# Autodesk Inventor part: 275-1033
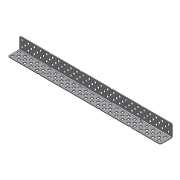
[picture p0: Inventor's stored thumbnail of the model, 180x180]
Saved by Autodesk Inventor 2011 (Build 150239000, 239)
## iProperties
Company: Autodesk Inc.
Created: 2005-08
Part Number: 275-1033
Document SubType Name: Sheet Metal
Designer: Autodesk Inc.
Density: 1 g/cm^3
Sheet Metal Rule: Default
Catalog Web Link: http://www.vexrobotics.com/chassis-kit.html
Description: 2x2x25 Bumper. This part has holes on 0.500" increments. This part is a versatile angle used in the medium chassis kit.
Vendor: Innovation First, Inc.
Author: Autodesk Inc.
Title: VEX Robotics Kit of Parts
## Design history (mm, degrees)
node "Face2"
  sketch "Sketch1"
    geometry: L1 (-158.75, 22.86)-(158.75, 22.86); L2 (-155.956, 19.939)-(-151.384, 19.939); L3 (-151.384, 19.939)-(-151.384, 15.367); L4 (-151.384, 15.367)-(-155.956, 15.367); L5 (-155.956, 15.367)-(-155.956, 19.939); L6 (-155.956, 7.239)-(-151.384, 7.239); L7 (-151.384, 7.239)-(-151.384, 2.667); L8 (-151.384, 2.667)-(-155.956, 2.667); L9 (-155.956, 2.667)-(-155.956, 7.239); L10 (-143.256, 19.939)-(-138.684, 19.939); L11 (-138.684, 19.939)-(-138.684, 15.367); L12 (-138.684, 15.367)-(-143.256, 15.367); L13 (-143.256, 15.367)-(-143.256, 19.939); L14 (-143.256, 7.239)-(-138.684, 7.239); L15 (-138.684, 7.239)-(-138.684, 2.667); L16 (-138.684, 2.667)-(-143.256, 2.667); L17 (-143.256, 2.667)-(-143.256, 7.239); L18 (-149.606, 9.017)-(-149.606, 13.589); L19 (-149.606, 13.589)-(-145.034, 13.589); L20 (-145.034, 9.017)-(-149.606, 9.017); L21 (-145.034, 13.589)-(-145.034, 9.017); L22 (-136.906, 9.017)-(-136.906, 13.589); L23 (-132.334, 9.017)-(-136.906, 9.017); L24 (-136.906, 13.589)-(-132.334, 13.589); L25 (-132.334, 13.589)-(-132.334, 9.017); L26 (-130.556, 15.367)-(-130.556, 19.939); L27 (-130.556, 2.667)-(-130.556, 7.239); L28 (-125.984, 2.667)-(-130.556, 2.667); L29 (-125.984, 7.239)-(-125.984, 2.667); L30 (-130.556, 7.239)-(-125.984, 7.239); L31 (-125.984, 15.367)-(-130.556, 15.367); L32 (-130.556, 19.939)-(-125.984, 19.939); L33 (-125.984, 19.939)-(-125.984, 15.367); L34 (-124.206, 9.017)-(-124.206, 13.589); L35 (-119.634, 9.017)-(-124.206, 9.017); L36 (-124.206, 13.589)-(-119.634, 13.589); L37 (-119.634, 13.589)-(-119.634, 9.017); L38 (-117.856, 15.367)-(-117.856, 19.939); L39 (-117.856, 2.667)-(-117.856, 7.239); L40 (-113.284, 2.667)-(-117.856, 2.667); L41 (-113.284, 7.239)-(-113.284, 2.667); L42 (-117.856, 7.239)-(-113.284, 7.239); L43 (-113.284, 15.367)-(-117.856, 15.367); L44 (-117.856, 19.939)-(-113.284, 19.939); L45 (-113.284, 19.939)-(-113.284, 15.367); L46 (-111.506, 9.017)-(-111.506, 13.589); L47 (-106.934, 9.017)-(-111.506, 9.017); L48 (-111.506, 13.589)-(-106.934, 13.589); L49 (-106.934, 13.589)-(-106.934, 9.017); L50 (-105.156, 15.367)-(-105.156, 19.939); L51 (-105.156, 2.667)-(-105.156, 7.239); L52 (-100.584, 2.667)-(-105.156, 2.667); L53 (-100.584, 7.239)-(-100.584, 2.667); L54 (-105.156, 7.239)-(-100.584, 7.239); L55 (-100.584, 15.367)-(-105.156, 15.367); L56 (-105.156, 19.939)-(-100.584, 19.939); L57 (-100.584, 19.939)-(-100.584, 15.367); L58 (-98.806, 9.017)-(-98.806, 13.589); L59 (-94.234, 9.017)-(-98.806, 9.017); L60 (-98.806, 13.589)-(-94.234, 13.589); L61 (-94.234, 13.589)-(-94.234, 9.017); L62 (-92.456, 15.367)-(-92.456, 19.939); L63 (-92.456, 2.667)-(-92.456, 7.239); L64 (-87.884, 2.667)-(-92.456, 2.667)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; 2 further points
    constraints: 600 end point, 12 parallel, 8 collinear, 7 horizontal, 6 perpendicular, 1 coincident, 1 midpoint, 552 other
    dimensions: "d20" = 2.794 distance between parallel lines of L192 L5; "d22" = 2.921 distance between parallel lines of L1 L2; "d23" = 22.86 distance between parallel lines of L191 L1; "d24" = 4.572 distance of L4.end L2.start; "d25" = 8.128 distance between parallel lines of L6 L4; "d26" = 4.572 distance of L8.end L6.start; "d125" = 317.5 distance of L190.end L191.end; "d126" = 4.572 distance of L2.start L2.end; "d127" = 4.572 distance of L18.end L19.end; "d128" = 4.572 distance of L19.end L20.start; "d129" = 9.017 distance between parallel lines of L191 L20; "d130" = 9.144 distance between parallel lines of L192 L18; "d133" = 15.494 distance between parallel lines of L192 L13; "d134" = 4.572 distance of L10.start L10.end
node "Flange8"
sketch "Sketch15"
  geometry: L1 (0, 0)-(0, 22.86) reference; L2 (0, 0)-(317.5, 0) reference; L3 (2.794, 2.921)-(7.366, 2.921); L4 (7.366, 2.921)-(7.366, 7.493); L5 (7.366, 7.493)-(2.794, 7.493); L6 (2.794, 7.493)-(2.794, 2.921); L7 (2.794, 15.621)-(7.366, 15.621); L8 (7.366, 15.621)-(7.366, 20.193); L9 (7.366, 20.193)-(2.794, 20.193); L10 (2.794, 20.193)-(2.794, 15.621); L11 (9.144, 9.017)-(13.716, 9.017); L12 (13.716, 9.017)-(13.716, 13.589); L13 (13.716, 13.589)-(9.144, 13.589); L14 (9.144, 13.589)-(9.144, 9.017); L15 (15.494, 15.621)-(20.066, 15.621); L16 (20.066, 15.621)-(20.066, 20.193); L17 (20.066, 20.193)-(15.494, 20.193); L18 (15.494, 20.193)-(15.494, 15.621); L19 (15.494, 7.493)-(20.066, 7.493); L20 (20.066, 7.493)-(20.066, 2.921); L21 (20.066, 2.921)-(15.494, 2.921); L22 (15.494, 2.921)-(15.494, 7.493); L23 (21.844, 13.589)-(21.844, 9.017); L24 (21.844, 9.017)-(26.416, 9.017); L25 (26.416, 13.589)-(21.844, 13.589); L26 (28.194, 2.921)-(28.194, 7.493); L27 (26.416, 9.017)-(26.416, 13.589); L28 (32.766, 7.493)-(32.766, 2.921); L29 (32.766, 2.921)-(28.194, 2.921); L30 (28.194, 7.493)-(32.766, 7.493); L31 (28.194, 20.193)-(28.194, 15.621); L32 (28.194, 15.621)-(32.766, 15.621); L33 (32.766, 15.621)-(32.766, 20.193); L34 (32.766, 20.193)-(28.194, 20.193); L35 (34.544, 13.589)-(34.544, 9.017); L36 (34.544, 9.017)-(39.116, 9.017); L37 (39.116, 13.589)-(34.544, 13.589); L38 (40.894, 2.921)-(40.894, 7.493); L39 (39.116, 9.017)-(39.116, 13.589); L40 (45.466, 7.493)-(45.466, 2.921); L41 (45.466, 2.921)-(40.894, 2.921); L42 (40.894, 7.493)-(45.466, 7.493); L43 (40.894, 20.193)-(40.894, 15.621); L44 (40.894, 15.621)-(45.466, 15.621); L45 (45.466, 15.621)-(45.466, 20.193); L46 (45.466, 20.193)-(40.894, 20.193); L47 (47.244, 13.589)-(47.244, 9.017); L48 (47.244, 9.017)-(51.816, 9.017); L49 (51.816, 13.589)-(47.244, 13.589); L50 (53.594, 2.921)-(53.594, 7.493); L51 (51.816, 9.017)-(51.816, 13.589); L52 (58.166, 7.493)-(58.166, 2.921); L53 (58.166, 2.921)-(53.594, 2.921); L54 (53.594, 7.493)-(58.166, 7.493); L55 (53.594, 20.193)-(53.594, 15.621); L56 (53.594, 15.621)-(58.166, 15.621); L57 (58.166, 15.621)-(58.166, 20.193); L58 (58.166, 20.193)-(53.594, 20.193); L59 (59.944, 13.589)-(59.944, 9.017); L60 (59.944, 9.017)-(64.516, 9.017); L61 (64.516, 13.589)-(59.944, 13.589); L62 (66.294, 2.921)-(66.294, 7.493); L63 (64.516, 9.017)-(64.516, 13.589); L64 (70.866, 7.493)-(70.866, 2.921)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; 1 further point
  constraints: 592 end point, 10 parallel, 8 collinear, 6 horizontal, 5 perpendicular, 552 other
  dimensions: "d148" = 2.921 distance between parallel lines of L2 L3; "d149" = 4.572 distance of L5.end L3.start; "d150" = 8.128 distance between parallel lines of L7 L5; "d151" = 4.572 distance of L9.end L7.start; "d152" = 2.794 distance between parallel lines of L1 L6; "d153" = 4.572 distance of L3.start L3.end; "d154" = 9.144 distance between parallel lines of L1 L14; "d155" = 4.572 distance of L11.start L11.end; "d156" = 4.572 distance of L13.end L11.start; "d157" = 15.494 distance between parallel lines of L1 L18; "d158" = 4.572 distance of L16.end L17.end; "d159" = 9.017 distance between parallel lines of L2 L11; "d162" = 12.7 distance of L19.end L28.start
cut "Cut4" sketch "Sketch15" dims "d167" = 1.27 (= Thickness), "d168" = 0
sketch "Sketch16" dims "d175" = 25.4
  geometry: L1 (-158.75, 22.86)-(158.75, 22.86) reference; L2 (-158.75, 0)-(-158.75, 22.86) reference; L3 (158.75, 0)-(-158.75, 0) reference; L4 (-158.75, 20.955)-(-156.845, 22.86); L5 (-156.845, 22.86)-(-160.655, 22.86); L6 (-160.655, 22.86)-(-158.75, 20.955); L7 (-95.25, 20.955)-(-93.345, 22.86); L8 (-93.345, 22.86)-(-97.155, 22.86); L9 (-97.155, 22.86)-(-95.25, 20.955); L10 (-31.75, 20.955)-(-29.845, 22.86); L11 (-29.845, 22.86)-(-33.655, 22.86); L12 (-33.655, 22.86)-(-31.75, 20.955); L13 (31.75, 20.955)-(33.655, 22.86); L14 (33.655, 22.86)-(29.845, 22.86); L15 (29.845, 22.86)-(31.75, 20.955); L16 (95.25, 20.955)-(97.155, 22.86); L17 (97.155, 22.86)-(93.345, 22.86); L18 (93.345, 22.86)-(95.25, 20.955); L19 (158.75, 20.955)-(160.655, 22.86); L20 (160.655, 22.86)-(156.845, 22.86); L21 (156.845, 22.86)-(158.75, 20.955); 1 further point
  constraints: 36 end point, 2 perpendicular, 2 point on line, 1 horizontal, 1 parallel, 30 other
  dimensions: "d169" = 1.905 horizontal distance of L4.start L4.end; "d172" = 63.5 distance of L4.end L7.end
cut "Cut5" sketch "Sketch16" dims "d177" = 1.27 (= Thickness), "d178" = 0
sketch "Sketch17" dims "d185" = 25.4
  geometry: L1 (0, 0)-(0, 22.86) reference; L2 (0, 0)-(317.5, 0) reference; L3 (317.5, 0)-(317.5, 22.86) reference; L4 (0, 1.905)-(1.905, 0); L5 (1.905, 0)-(-1.905, 0); L6 (-1.905, 0)-(0, 1.905); L7 (63.5, 1.905)-(65.405, 0); L8 (65.405, 0)-(61.595, 0); L9 (61.595, 0)-(63.5, 1.905); L10 (127, 1.905)-(128.905, 0); L11 (128.905, 0)-(125.095, 0); L12 (125.095, 0)-(127, 1.905); L13 (190.5, 1.905)-(192.405, 0); L14 (192.405, 0)-(188.595, 0); L15 (188.595, 0)-(190.5, 1.905); L16 (254, 1.905)-(255.905, 0); L17 (255.905, 0)-(252.095, 0); L18 (252.095, 0)-(254, 1.905); L19 (317.5, 1.905)-(319.405, 0); L20 (319.405, 0)-(315.595, 0); L21 (315.595, 0)-(317.5, 1.905); 1 further point
  constraints: 36 end point, 3 perpendicular, 2 point on line, 1 horizontal, 30 other
  dimensions: "d179" = 1.905 horizontal distance of L5.end L4.start; "d182" = 63.5 distance of L4.end L7.end
cut "Cut6" sketch "Sketch17" dims "d187" = 1.27 (= Thickness), "d188" = 0
sketch "Sketch18" dims "d196" = 25.4
  geometry: L1 (317.5, 0)-(0, 0) reference; L2 (65.405, -22.86)-(125.095, -22.86) reference; L3 (61.595, 1.118)-(63.5, -0.787); L4 (63.5, -0.787)-(65.405, 1.118); L5 (65.405, 1.118)-(63.5, 3.023); L6 (63.5, 3.023)-(61.595, 1.118); L7 (128.905, 1.118)-(127, 3.023); L8 (125.095, 1.118)-(127, -0.787); L9 (127, 3.023)-(125.095, 1.118); L10 (127, -0.787)-(128.905, 1.118); L11 (192.405, 1.118)-(190.5, 3.023); L12 (188.595, 1.118)-(190.5, -0.787); L13 (190.5, 3.023)-(188.595, 1.118); L14 (190.5, -0.787)-(192.405, 1.118); L15 (255.905, 1.118)-(254, 3.023); L16 (252.095, 1.118)-(254, -0.787); L17 (254, 3.023)-(252.095, 1.118); L18 (254, -0.787)-(255.905, 1.118); 2 further points
  constraints: 32 end point, 2 parallel, 2 perpendicular, 1 horizontal, 1 horizontal alignment, 1 vertical alignment, 24 other
  dimensions: "d189" = 1.1176 distance from line of L1 L3.start; "d190" = 1.905 horizontal distance of L5.end L3.start; "d193" = 63.5 distance of L4.end L7.start
cut "Cut7" sketch "Sketch18" dims "d198" = 1.27 (derived), "d199" = 0
body "Solid1"
face "Plate9" dims "Thickness" = 1.27
sketch "Sketch14"
  geometry: L1 (0, 22.86)-(-317.5, 22.86); L2 (-317.5, 22.86)-(-317.5, 0); 2 other entities
  constraints: 4 end point, 4 other
face "Plate10" dims "d138" = 1.27 (= BendReliefWidth), "d139" = 0.635 (= BendReliefDepth), "d140" = 2.54 (= MinimumRemnant), "d141" = 1.27 (= BendRadius), "d142" = 25.4, "d143" = 90 deg, "d144" = 1.27 (= BendRadius), "d145" = 5.08 (= CornerReliefSize), "d146" = 1.27 (= GapSize), "d147" = 1.27 (= JacobiRadiusSize), "SeamGap" = 0.00508, "Thickness" = 1.27
bend "Bend8" dims "d138" = 1.27 (= BendReliefWidth), "d139" = 0.635 (= BendReliefDepth), "d140" = 2.54 (= MinimumRemnant), "d141" = 1.27 (= BendRadius), "d142" = 25.4, "d143" = 90 deg, "d144" = 1.27 (= BendRadius), "SeamGap" = 0.00508, "Thickness" = 1.27
feature "Corner1" dims "d142" = 25.4, "d143" = 90 deg, "d145" = 5.08 (= CornerReliefSize), "d146" = 1.27 (= GapSize), "d147" = 1.27 (= JacobiRadiusSize)
other parameters: "BendRadius" = 1.27 (= Thickness), "BendReliefWidth" = 1.27 (= Thickness), "BendReliefDepth" = 0.635 (= 0.5 x Thickness), "CornerReliefSize" = 5.08 (= 4 x Thickness), "MinimumRemnant" = 2.54 (= 2 x Thickness), "TransitionRadius" = 1.27 (= BendRadius), "d13" = 12.7, "d16" = 25.4, "d27" = 1.27 (= BendRadius), "JacobiRadiusSize" = 1.27 (= BendRadius), "GapSize" = 1.27 (= Thickness), "d136" = 1.27 (= BendRadius), "d165" = 25.4
